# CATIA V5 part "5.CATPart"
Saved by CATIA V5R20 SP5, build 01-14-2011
Part number: 5
Bounding box of the stored display mesh (mm): x -106.5 to -93.5, y -14 to 16, z 3.5 to 16.5
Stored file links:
  F:\CAD\很靠后、\5.CATPart
  F:\CAD\很靠后、\4.CATPart
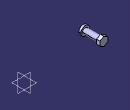
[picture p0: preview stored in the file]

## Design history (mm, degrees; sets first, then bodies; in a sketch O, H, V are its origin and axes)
Body1 (main body)
Body2
  Sketch1 on zx-plane, origin (0, 0, 0), H (-1, 0, 0), V (0, 0, 1)
    circle A1 centre (100, 10) radius 4
    radius A1 = 4
  Pad1: profile Sketch1, direction (0, 1, 0), length 11, mirrored extent
  Sketch2 on start face of Pad1, origin (0, -11, 0), H (1, 0, 0), V (0, 0, 1)
    circle A1 centre (-100, 10) radius 6.5
    radius A1 = 6.5
  Pad2: profile Sketch2, direction (0, -1, 0), length 3
  Sketch3 on end face of Pad1, origin (0, 11, 0), H (-1, 0, 0), V (0, 0, 1)
    point P1 (100, 10)
    point P2 (105.6292, 6.75)
    point P3 (105.6292, 13.25)
    point P4 (100, 16.5)
    point P5 (94.3708, 13.25)
    point P6 (94.3708, 6.75)
    point P7 (100, 3.5)
    point P8 (105.6292, 10)
    line L1 (105.6292, 6.75) -> (105.6292, 13.25)
    line L2 (105.6292, 13.25) -> (100, 16.5)
    line L3 (100, 16.5) -> (94.3708, 13.25)
    line L4 (94.3708, 13.25) -> (94.3708, 6.75)
    line L5 (94.3708, 6.75) -> (100, 3.5)
    line L6 (100, 3.5) -> (105.6292, 6.75)
    construction line L7 (100, 10) -> (105.6292, 10)
    construction circle A1 centre (100, 10) radius 6.5
    construction arc A2 centre (94.3708, 6.75) radius 6.5 from (94.3708, 13.25) to (100, 3.5) cw
    construction arc A3 centre (105.6292, 13.25) radius 6.5 from (100, 16.5) to (105.6292, 6.75) ccw
    radius A1 = 6.5
    coincidence: A1 P2, A1 P3, A1 P4, A1 P5, A1 P6, A1 P7, A2 P1, A3 P1
    midpoint: P8 L1
    parallelism: L1 L4
  Pad3: profile Sketch3, direction (0, 1, 0), length 5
